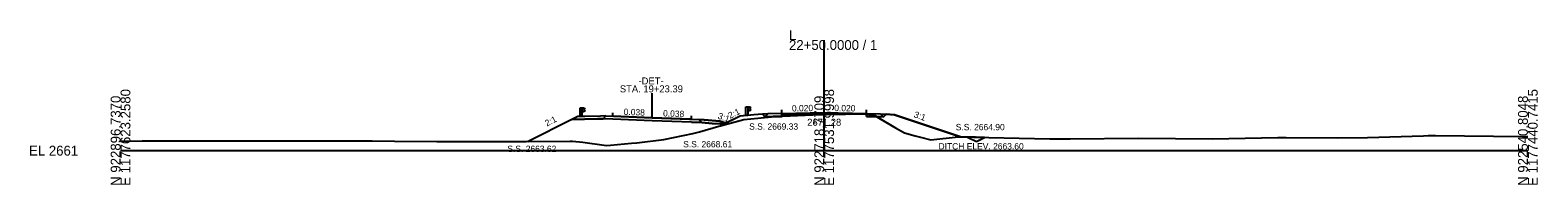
# Model space of a CAD drawing. Extents: x -26 to 1403, y -10 to 9563.
# Drawn here: x 974.3 to 1402.8, y 2490.3 to 2534.2 of the extents above; entities that cross this region are included whole.
import ezdxf

# ---------------------------------------------------------------- set-up
doc = ezdxf.new("R2010")
doc.units = 0
for name, color, linetype in [('Exist Cross Section Cell', 7, 'Continuous'), ('Exist XS Center Line Elevation Label', 7, 'Continuous'), ('Exist XS Ground Line', 7, 'Continuous'), ('Prop XS DDE Earthwork Shape', 7, 'Continuous'), ('Prop XS Ditch Slope Text', 7, 'Continuous'), ('Prop XS Ditch Standard Text', 7, 'Continuous'), ('Prop XS Dump Level', 7, 'Continuous'), ('Prop XS Earthwork Shape', 7, 'Continuous'), ('Prop XS EOT Tick Mark', 7, 'Continuous'), ('Prop XS Finish Grade', 7, 'Continuous'), ('Prop XS Finish Grade Earthwork', 7, 'Continuous'), ('Prop XS Finish Grade Paved Shoulder', 7, 'Continuous'), ('Prop XS Finish Grade Pavement', 7, 'Continuous'), ('Prop XS Guardrail', 7, 'Continuous'), ('Prop XS Pvmt Edge Slope', 7, 'Continuous'), ('Prop XS SE Text', 7, 'Continuous'), ('Prop XS Shoulder Borrow Shape', 7, 'Continuous'), ('Prop XS Side Slope Text', 7, 'Continuous'), ('Prop XS SS Elevation Text', 7, 'Continuous'), ('Prop XS Subgrade Earthwork', 7, 'Continuous'), ('Prop XS Vertical Lines', 7, 'Continuous'), ('Prop XS Wedging', 7, 'Continuous')]:
    doc.layers.add(name, color=color, linetype=linetype)

msp = doc.modelspace()

# ---------------------------------------------------------------- linework, layer by layer
at = {"layer": 'Exist Cross Section Cell'}
for p, q in [((1200, 2500), (1200, 2531.38)), ((1000, 2500), (1200, 2500)), ((1200, 2500), (1400, 2500))]:
    msp.add_line(p, q, dxfattribs=at)
at = {"layer": 'Exist XS Ground Line'}
for p, q in [((1164.59, 2505.33), (1170.04, 2506.92)), ((1170.04, 2506.92), (1177.14, 2508.84)), ((1177.14, 2508.84), (1181.12, 2509.22)), ((1181.12, 2509.22), (1185.99, 2509.71)), ((1185.99, 2509.71), (1198.95, 2510.23)), ((1198.95, 2510.23), (1200.23, 2510.29)), ((1200.23, 2510.29), (1200.66, 2510.29)), ((1200.66, 2510.29), (1211.57, 2510.46)), ((1211.57, 2510.46), (1214.28, 2510.01)), ((1214.28, 2510.01), (1220.3, 2506.5)), ((1000, 2502.71), (1001.05, 2502.71)), ((1001.05, 2502.71), (1006.15, 2502.77)), ((1006.15, 2502.77), (1011.41, 2502.81)), ((1011.41, 2502.81), (1030.7, 2502.77)), ((1030.7, 2502.77), (1038.62, 2502.76)), ((1038.62, 2502.76), (1042.62, 2502.76)), ((1042.62, 2502.76), (1057.62, 2502.75)), ((1057.62, 2502.75), (1071.54, 2502.74)), ((1071.54, 2502.74), (1077.84, 2502.73)), ((1077.84, 2502.73), (1089.91, 2502.6)), ((1115.33, 2502.62), (1127.84, 2502.73)), ((1127.84, 2502.73), (1128.48, 2502.73)), ((1128.48, 2502.73), (1131.42, 2502.36)), ((1146.73, 2502.23), (1154.38, 2503.16)), ((1154.38, 2503.16), (1162.68, 2504.89)), ((1162.68, 2504.89), (1164.59, 2505.33)), ((1220.3, 2506.5), (1222.79, 2505.03)), ((1222.79, 2505.03), (1225.86, 2504.21)), ((1225.86, 2504.21), (1227.39, 2503.81)), ((1227.39, 2503.81), (1230.29, 2503.06)), ((1230.29, 2503.06), (1238.1, 2503.91)), ((1238.1, 2503.91), (1264.16, 2503.38)), ((1264.16, 2503.38), (1266.07, 2503.35)), ((1266.07, 2503.35), (1269.9, 2503.39)), ((1269.9, 2503.39), (1289.29, 2503.58)), ((1289.29, 2503.58), (1310.33, 2503.32)), ((1310.33, 2503.32), (1328.94, 2503.7)), ((1328.94, 2503.7), (1331.31, 2503.75)), ((1331.31, 2503.75), (1345.86, 2503.64)), ((1345.86, 2503.64), (1354.42, 2503.69)), ((1354.42, 2503.69), (1370.33, 2504.25)), ((1370.33, 2504.25), (1371.67, 2504.28)), ((1371.67, 2504.28), (1373.73, 2504.3)), ((1373.73, 2504.3), (1398.52, 2504.06)), ((1398.52, 2504.06), (1400, 2504.03)), ((1089.91, 2502.6), (1098.74, 2502.57)), ((1098.74, 2502.57), (1103.19, 2502.59)), ((1103.19, 2502.59), (1115.33, 2502.62)), ((1131.42, 2502.36), (1138.14, 2501.47)), ((1138.14, 2501.47), (1139.23, 2501.57)), ((1139.23, 2501.57), (1145.23, 2502.09)), ((1145.23, 2502.09), (1146.73, 2502.23))]:
    msp.add_line(p, q, dxfattribs=at)
at = {"layer": 'Prop XS DDE Earthwork Shape'}
for p, q in [((1242.97, 2503.81), (1238.74, 2503.9)), ((1238.74, 2503.9), (1240.74, 2503.86)), ((1240.74, 2503.86), (1243.26, 2502.6)), ((1243.08, 2503.76), (1242.97, 2503.81)), ((1243.18, 2503.81), (1243.08, 2503.76)), ((1245.57, 2503.76), (1243.18, 2503.81)), ((1243.26, 2502.6), (1245.57, 2503.76))]:
    msp.add_line(p, q, dxfattribs=at)
at = {"layer": 'Prop XS Dump Level'}
for p, q in [((1137.95, 2509.84), (1151.13, 2509.34)), ((1151.13, 2509.34), (1139.95, 2509.76)), ((1162.32, 2508.92), (1151.13, 2509.34)), ((1151.13, 2509.34), (1164.32, 2508.84)), ((1188, 2510.55), (1200, 2510.79)), ((1200, 2510.79), (1212, 2510.55))]:
    msp.add_line(p, q, dxfattribs=at)
at = {"layer": 'Prop XS Earthwork Shape'}
for p, q in [((1128.31, 2508.84), (1115.88, 2502.62)), ((1135.58, 2509), (1128.31, 2508.84)), ((1137.15, 2509.03), (1135.58, 2509)), ((1139.95, 2508.93), (1137.15, 2509.03)), ((1151.13, 2508.5), (1139.95, 2508.93)), ((1162.32, 2508.08), (1151.13, 2508.5)), ((1165.18, 2507.97), (1162.32, 2508.08)), ((1164.59, 2505.33), (1170.04, 2506.92)), ((1168.17, 2507.73), (1165.18, 2507.97)), ((1171.68, 2507.63), (1168.17, 2507.73)), ((1170.04, 2506.92), (1170.51, 2507.04)), ((1170.51, 2507.04), (1171.68, 2507.63)), ((1171.68, 2507.63), (1170.51, 2507.04)), ((1171.68, 2507.63), (1170.51, 2507.04)), ((1170.51, 2507.04), (1172.58, 2507.61)), ((1170.51, 2507.04), (1172.58, 2507.61)), ((1172.58, 2507.61), (1171.68, 2507.63)), ((1172.58, 2507.61), (1171.68, 2507.63)), ((1176.08, 2509.83), (1172.01, 2507.8)), ((1172.01, 2507.8), (1172.58, 2507.61)), ((1172.58, 2507.61), (1177.14, 2508.84)), ((1177.14, 2508.84), (1181.12, 2509.22)), ((1182.43, 2510.34), (1180, 2510.15)), ((1181.12, 2509.22), (1185.52, 2509.66)), ((1183.15, 2509.62), (1182.43, 2510.34)), ((1185.52, 2509.66), (1183.15, 2509.62)), ((1185.99, 2509.71), (1185.52, 2509.66)), ((1185.52, 2509.66), (1188, 2509.71)), ((1188, 2509.79), (1185.99, 2509.71)), ((1188, 2509.71), (1188, 2509.79)), ((1214.28, 2510.01), (1212, 2510.39)), ((1212, 2510.39), (1212, 2509.71)), ((1212, 2509.71), (1214.89, 2509.65)), ((1214.89, 2509.65), (1214.28, 2510.01)), ((1216.85, 2509.62), (1214.89, 2509.65)), ((1214.89, 2509.65), (1220.3, 2506.5)), ((1217.57, 2510.34), (1216.85, 2509.62)), ((1220, 2510.15), (1217.57, 2510.34)), ((1238.74, 2503.9), (1220, 2510.15)), ((1115.88, 2502.62), (1127.84, 2502.73)), ((1127.84, 2502.73), (1128.48, 2502.73)), ((1128.48, 2502.73), (1131.42, 2502.36)), ((1146.73, 2502.23), (1154.38, 2503.16)), ((1154.38, 2503.16), (1162.68, 2504.89)), ((1162.68, 2504.89), (1164.59, 2505.33)), ((1220.3, 2506.5), (1222.79, 2505.03)), ((1222.79, 2505.03), (1225.86, 2504.21)), ((1225.86, 2504.21), (1227.39, 2503.81)), ((1227.39, 2503.81), (1230.29, 2503.06)), ((1230.29, 2503.06), (1238.1, 2503.91)), ((1238.1, 2503.91), (1238.74, 2503.9)), ((1131.42, 2502.36), (1138.14, 2501.47)), ((1138.14, 2501.47), (1139.23, 2501.57)), ((1139.23, 2501.57), (1145.23, 2502.09)), ((1145.23, 2502.09), (1146.73, 2502.23))]:
    msp.add_line(p, q, dxfattribs=at)
msp.add_lwpolyline([(1180, 2510.15), (1178.26, 2510.01), (1177.76, 2509.97), (1176.08, 2509.83)], dxfattribs=at)
at = {"layer": 'Prop XS EOT Tick Mark'}
for p, q in [((1188, 2510.55), (1188, 2511.55)), ((1212, 2510.55), (1212, 2511.55)), ((1139.95, 2509.76), (1139.95, 2510.76)), ((1162.32, 2508.92), (1162.32, 2509.92))]:
    msp.add_line(p, q, dxfattribs=at)
at = {"layer": 'Prop XS Finish Grade'}
for p, q in [((1137.95, 2509.84), (1136.38, 2509.8)), ((1164.32, 2508.84), (1165.92, 2508.71)), ((1184, 2510.47), (1182.43, 2510.34)), ((1216, 2510.47), (1217.57, 2510.34))]:
    msp.add_line(p, q, dxfattribs=at)
at = {"layer": 'Prop XS Finish Grade Earthwork'}
for p, q in [((1128.31, 2508.84), (1115.88, 2502.62)), ((1129.95, 2509.66), (1128.31, 2508.84)), ((1131.95, 2509.7), (1129.95, 2509.66)), ((1136.38, 2509.8), (1131.95, 2509.7)), ((1165.92, 2508.71), (1170.32, 2508.36)), ((1170.32, 2508.36), (1172.58, 2507.61)), ((1176.08, 2509.83), (1170.51, 2507.04)), ((1180, 2510.15), (1176.08, 2509.83)), ((1182.43, 2510.34), (1180, 2510.15)), ((1217.57, 2510.34), (1220, 2510.15)), ((1220, 2510.15), (1238.74, 2503.9)), ((1238.74, 2503.9), (1240.74, 2503.86)), ((1240.74, 2503.86), (1243.26, 2502.6)), ((1243.26, 2502.6), (1245.57, 2503.76))]:
    msp.add_line(p, q, dxfattribs=at)
at = {"layer": 'Prop XS Finish Grade Paved Shoulder'}
for p, q in [((1188, 2510.55), (1184, 2510.47)), ((1212, 2510.55), (1216, 2510.47))]:
    msp.add_line(p, q, dxfattribs=at)
at = {"layer": 'Prop XS Finish Grade Pavement'}
for p, q in [((1137.95, 2509.84), (1151.13, 2509.34)), ((1151.13, 2509.34), (1164.32, 2508.84)), ((1188, 2510.55), (1200, 2510.79)), ((1200, 2510.79), (1212, 2510.55))]:
    msp.add_line(p, q, dxfattribs=at)
at = {"layer": 'Prop XS Guardrail'}
for p, q in [((1130.63, 2512.18), (1131.13, 2512.18)), ((1130.63, 2509.68), (1130.63, 2512.18)), ((1131.13, 2512.18), (1131.63, 2512.18)), ((1131.13, 2512.18), (1131.13, 2509.68)), ((1131.63, 2512.18), (1131.92, 2511.98)), ((1131.92, 2511.86), (1131.63, 2511.66)), ((1131.63, 2511.66), (1131.63, 2511.56)), ((1131.63, 2511.56), (1131.92, 2511.36)), ((1131.92, 2511.24), (1131.63, 2511.04)), ((1131.92, 2511.98), (1131.95, 2511.92)), ((1131.95, 2511.92), (1131.92, 2511.86)), ((1131.92, 2511.36), (1131.95, 2511.3)), ((1131.95, 2511.3), (1131.92, 2511.24)), ((1177.76, 2512.47), (1178.26, 2512.47)), ((1177.76, 2509.97), (1177.76, 2512.47)), ((1178.26, 2512.47), (1178.76, 2512.47)), ((1178.26, 2512.47), (1178.26, 2509.97)), ((1178.76, 2511.33), (1178.26, 2511.33)), ((1178.76, 2512.47), (1179.05, 2512.27)), ((1179.05, 2512.15), (1178.76, 2511.95)), ((1178.76, 2511.95), (1178.76, 2511.85)), ((1178.76, 2511.85), (1179.05, 2511.65)), ((1179.05, 2511.53), (1178.76, 2511.33)), ((1179.05, 2512.27), (1179.08, 2512.21)), ((1179.08, 2512.21), (1179.05, 2512.15)), ((1179.05, 2511.65), (1179.08, 2511.59)), ((1179.08, 2511.59), (1179.05, 2511.53)), ((1131.63, 2511.04), (1131.13, 2511.04))]:
    msp.add_line(p, q, dxfattribs=at)
at = {"layer": 'Prop XS Pvmt Edge Slope'}
for p, q in [((1137.95, 2509.84), (1137.15, 2509.03)), ((1164.32, 2508.84), (1165.18, 2507.97)), ((1184, 2510.47), (1183.15, 2509.62)), ((1216, 2510.47), (1216.85, 2509.62))]:
    msp.add_line(p, q, dxfattribs=at)
at = {"layer": 'Prop XS Shoulder Borrow Shape'}
for p, q in [((1129.95, 2509.66), (1128.31, 2508.84)), ((1128.31, 2508.84), (1135.58, 2509)), ((1130.63, 2509.68), (1129.95, 2509.66)), ((1130.63, 2509.68), (1130.63, 2509.68)), ((1136.38, 2509.8), (1131.95, 2509.7)), ((1135.58, 2509), (1137.15, 2509.03)), ((1137.95, 2509.84), (1136.38, 2509.8)), ((1137.15, 2509.03), (1137.95, 2509.84)), ((1165.92, 2508.71), (1164.32, 2508.84)), ((1164.32, 2508.84), (1165.18, 2507.97)), ((1165.18, 2507.97), (1168.17, 2507.73)), ((1170.32, 2508.36), (1165.92, 2508.71)), ((1168.17, 2507.73), (1171.68, 2507.63)), ((1172.01, 2507.8), (1170.32, 2508.36)), ((1171.68, 2507.63), (1172.01, 2507.8))]:
    msp.add_line(p, q, dxfattribs=at)
for points in [[(1131.95, 2509.7), (1131.13, 2509.69), (1130.63, 2509.68)], [(1130.63, 2509.68), (1130.63, 2509.68)]]:
    msp.add_lwpolyline(points, dxfattribs=at)
at = {"layer": 'Prop XS Subgrade Earthwork'}
for p, q in [((1135.58, 2509), (1128.31, 2508.84)), ((1137.15, 2509.03), (1135.58, 2509)), ((1139.95, 2508.93), (1137.15, 2509.03)), ((1151.13, 2508.5), (1139.95, 2508.93)), ((1162.32, 2508.08), (1151.13, 2508.5)), ((1162.32, 2508.08), (1165.18, 2507.97)), ((1168.17, 2507.73), (1165.18, 2507.97)), ((1172.58, 2507.61), (1168.17, 2507.73)), ((1183.15, 2509.62), (1182.43, 2510.34)), ((1188, 2509.71), (1183.15, 2509.62)), ((1188, 2509.71), (1188, 2509.79)), ((1212, 2509.71), (1212, 2510.39)), ((1212, 2509.71), (1216.85, 2509.62)), ((1216.85, 2509.62), (1217.57, 2510.34))]:
    msp.add_line(p, q, dxfattribs=at)
at = {"layer": 'Prop XS Vertical Lines'}
msp.add_line((1151.13, 2509.34), (1151.13, 2516.34), dxfattribs=at)
at = {"layer": 'Prop XS Wedging'}
for points in [[(1188, 2509.79), (1188, 2510.3), (1198.95, 2510.52), (1200, 2510.54), (1200.23, 2510.53), (1200.66, 2510.52), (1207.17, 2510.39), (1207.17, 2510.39), (1200.66, 2510.29), (1200.23, 2510.28), (1200, 2510.27), (1198.95, 2510.23)], [(1188, 2509.79), (1188, 2510.3), (1198.95, 2510.52), (1200, 2510.54), (1200.23, 2510.53), (1200.66, 2510.52), (1201.89, 2510.5), (1202.07, 2510.31), (1200.66, 2510.29), (1200.23, 2510.28), (1200, 2510.27), (1198.95, 2510.23)], [(1188, 2509.79), (1188, 2510.05), (1188.31, 2510.05), (1188.55, 2509.81)]]:
    msp.add_lwpolyline(points, close=True, dxfattribs=at)

# ---------------------------------------------------------------- texts
at = {"layer": 'Exist Cross Section Cell'}
for s, p in [('L', (1190, 2531.38)), ('22+50.0000 / 1', (1190, 2528.58)), ('EL 2661', (974, 2498.6))]:
    msp.add_text(s, height=2.8, dxfattribs=at).set_placement(p)
for s, p in [('E 1177623.2580', (1002.8, 2490)), ('E 1177531.9998', (1202.8, 2490)), ('E 1177440.7415', (1402.8, 2490)), ('N 922896.7370', (1000, 2490)), ('N 922718.7709', (1200, 2490)), ('N 922540.8048', (1400, 2490))]:
    msp.add_text(s, height=2.8, rotation=90, dxfattribs=at).set_placement(p)
at = {"layer": 'Exist XS Center Line Elevation Label'}
msp.add_text('2671.28', height=2, dxfattribs=at).set_placement((1195.17, 2507.05))
at = {"layer": 'Prop XS Ditch Slope Text'}
msp.add_text('3:1', height=1.8, rotation=340.807, dxfattribs=at).set_placement((1169.6, 2509.13))
at = {"layer": 'Prop XS Ditch Standard Text'}
msp.add_text('DITCH ELEV. 2663.60', height=1.8, dxfattribs=at).set_placement((1232.49, 2500.33))
at = {"layer": 'Prop XS Dump Level'}
for s, p in [('Case1', (1131.95, 2509.55)), ('Case1', (1170.32, 2508.24)), ('Case2', (1180, 2510.11)), ('Case2', (1220, 2510.11))]:
    msp.add_text(s, height=0.04, dxfattribs=at).set_placement(p)
at = {"layer": 'Prop XS SE Text'}
for s, rotation, p in [('0.038', 357.8296, (1142.98, 2510.15)), ('0.038', 357.8355, (1154.17, 2509.72)), ('0.020', 1.1458, (1190.84, 2511.1)), ('0.020', 358.8542, (1202.84, 2511.23))]:
    msp.add_text(s, height=1.8, rotation=rotation, dxfattribs=at).set_placement(p)
at = {"layer": 'Prop XS Side Slope Text'}
for s, rotation, p in [('2:1', 26.5651, (1173.26, 2509.02)), ('2:1', 26.5651, (1121.16, 2506.82)), ('3:1', 340.7648, (1225.34, 2509.52))]:
    msp.add_text(s, height=1.8, rotation=rotation, dxfattribs=at).set_placement(p)
at = {"layer": 'Prop XS SS Elevation Text'}
for s, p in [('S.S. 2669.33', (1178.67, 2505.95)), ('S.S. 2664.90', (1237.39, 2505.79)), ('S.S. 2668.61', (1159.91, 2500.92)), ('S.S. 2663.62', (1109.95, 2499.62))]:
    msp.add_text(s, height=1.8, dxfattribs=at).set_placement(p)
at = {"layer": 'Prop XS Vertical Lines'}
for s, p in [('-DET-', (1147.22, 2518.78)), ('STA. 19+23.39', (1141.92, 2516.53))]:
    msp.add_text(s, height=2, dxfattribs=at).set_placement(p)

doc.saveas('drawing.dxf')
